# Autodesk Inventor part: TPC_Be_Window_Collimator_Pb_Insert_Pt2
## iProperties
Shininess: 64.0
Length Units: 11269
Angle Units: 11279
Time Units: 11290
Mass Units: 11283
Length Display Precision: 3
Angle Display Precision: 2
Compacted: True
Part Number: TPC_Be_Window_Collimator_Pb_Insert_Pt2
Document SubType Name: Sheet Metal
Created: 2004-07
Material: Lead
Designer: John Blackburn
Manufacturer: Standard
Standards Organization: Custom
Density: 0.0
Volumn: 0.0
Area: 0.0
PropertySet Name: Model Information
Control State: 0
Master: False
Checked Out: False
Author: John Blackburn
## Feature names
1. Revolution1
